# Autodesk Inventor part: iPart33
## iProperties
Created: 2005-03
Part Number: iPart33
Document SubType Name: Modeling
Designer: CADCIM
Manufacturer: Standard
Standards Organization: Custom
Author: CADCIM
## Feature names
1. Derived Body1 [Tagging]
